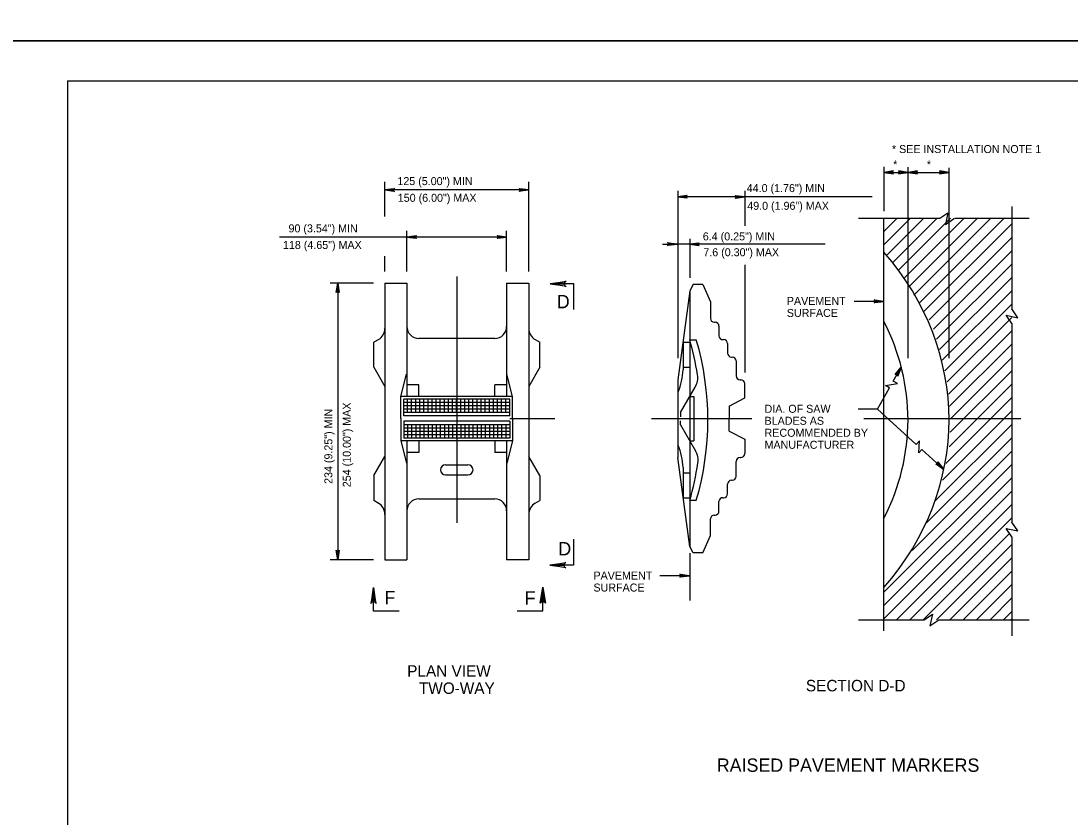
# Model space of a CAD drawing. Extents: x 639362 to 641108, y 298458 to 299646.
# Drawn here: x 640225.9 to 640619.2, y 298760.6 to 299059.1 of the extents above; entities that cross this region are included whole.
import ezdxf

# ---------------------------------------------------------------- set-up
doc = ezdxf.new("R2010")
doc.units = 0
for name, color, linetype in [('1', 7, 'Continuous'), ('2', 7, 'Continuous'), ('3', 7, 'Continuous'), ('PLT-BNDY', 7, 'Continuous')]:
    doc.layers.add(name, color=color, linetype=linetype)

# ---------------------------------------------------------------- blocks, each defined once
blk = doc.blocks.new('RARROW')
at = {"layer": '3'}
blk.add_lwpolyline([(-2.2695, 0.285), (-2.184875, 0.12075), (0, 0), (-2.2695, 0.285), (-2.38575, 0.384625), (0, 0), (-2.183125, -0.108), (-2.262875, -0.2705), (0, 0), (-2.38575, -0.379125), (-2.262875, -0.2705)], dxfattribs=at)

msp = doc.modelspace()

# ---------------------------------------------------------------- linework, layer by layer
at = {"layer": '1'}
for q in [(641029.31, 299036.63), (640243.31, 298472.63)]:
    msp.add_line((640243.31, 299036.63), q, dxfattribs=at)
at = {"layer": '2'}
for p, q in [((640549.4, 299004.47), (640549.4, 298987.85)), ((640549.4, 299002.33), (640573.84, 299002.33)), ((640558.46, 298932.66), (640558.46, 299004.34)), ((640573.84, 298932.66), (640573.84, 299004.07)), ((640362.29, 298985.8), (640362.29, 298998.87)), ((640416.24, 298965.15), (640416.24, 298998.87)), ((640416.24, 298995.79), (640362.29, 298995.79)), ((640472.13, 298995.38), (640472.13, 298932.71)), ((640497.22, 298995.38), (640497.22, 298982.37)), ((640544.99, 298993.14), (640472.13, 298993.14)), ((640570.36, 298985.17), (640573.44, 298987.22)), ((640573.44, 298987.22), (640572.53, 298982.82)), ((640597.33, 298989.51), (640597.33, 298951.16)), ((640539.93, 298985.17), (640570.36, 298985.17)), ((640549.4, 298985.16), (640549.41, 298985.17)), ((640549.4, 298980.15), (640554.42, 298985.17)), ((640549.4, 298975.14), (640559.43, 298985.17)), ((640549.4, 298830.51), (640549.4, 298985.17)), ((640550.44, 298971.18), (640564.44, 298985.17)), ((640552.68, 298968.41), (640569.44, 298985.17)), ((640554.92, 298965.64), (640574.45, 298985.17)), ((640556.84, 298962.55), (640579.46, 298985.17)), ((640558.75, 298959.45), (640584.47, 298985.17)), ((640560.66, 298956.35), (640589.48, 298985.17)), ((640562.56, 298953.25), (640594.49, 298985.17)), ((640564.45, 298950.13), (640597.33, 298983.01)), ((640572.53, 298982.82), (640575.83, 298985.17)), ((640576.1, 298985.17), (640603.86, 298985.17)), ((640407.94, 298978.12), (640322.8, 298978.12)), ((640370.59, 298965.15), (640370.59, 298980.4)), ((640407.94, 298965.15), (640407.94, 298980.4)), ((640466.45, 298975.45), (640471.88, 298975.45)), ((640527.35, 298975.45), (640472.13, 298975.45)), ((640476.61, 298977.46), (640476.61, 298962.86)), ((640566.35, 298947.02), (640597.33, 298978)), ((640362.29, 298965.15), (640362.29, 298971)), ((640567.97, 298943.62), (640597.33, 298972.99)), ((640497.22, 298967.65), (640497.22, 298927.34)), ((640569.13, 298939.78), (640597.33, 298967.98)), ((640389.27, 298963.3), (640389.27, 298870.92)), ((640570.29, 298935.93), (640597.33, 298962.97)), ((640357.99, 298960.85), (640341.84, 298960.85)), ((640344.63, 298960.85), (640344.63, 298857.09)), ((640362.29, 298960.85), (640362.29, 298857.09)), ((640362.29, 298960.85), (640370.59, 298960.85)), ((640370.59, 298960.85), (640370.59, 298918.31)), ((640407.94, 298960.85), (640416.24, 298960.85)), ((640407.94, 298960.85), (640407.94, 298918.31)), ((640416.24, 298960.85), (640416.24, 298857.09)), ((640433.12, 298960.62), (640424.24, 298960.62)), ((640433.12, 298951), (640433.12, 298960.62)), ((640477.94, 298960.33), (640476.61, 298957.95)), ((640481.5, 298960.33), (640477.94, 298960.33)), ((640481.5, 298960.33), (640484.36, 298953.79)), ((640476.61, 298957.95), (640472.13, 298924.52)), ((640476.61, 298957.95), (640476.61, 298862.07)), ((640571.3, 298931.94), (640597.33, 298957.97)), ((640484.36, 298953.79), (640484.36, 298947.61)), ((640549.4, 298953.95), (640538.26, 298953.95)), ((640572.26, 298927.89), (640597.33, 298952.96)), ((640599.68, 298947.87), (640597.33, 298951.16)), ((640573.15, 298923.77), (640597.33, 298947.95)), ((640597.33, 298945.7), (640595.28, 298948.78)), ((640595.28, 298948.78), (640599.68, 298947.87)), ((640485.82, 298946.15), (640486.12, 298946.15)), ((640487.58, 298944.69), (640487.58, 298941.1)), ((640573.6, 298919.21), (640597.33, 298942.94)), ((640597.33, 298945.7), (640597.33, 298871.2)), ((640359.85, 298939.63), (640358.14, 298938.65)), ((640403.52, 298940.1), (640375.02, 298940.1)), ((640418.68, 298939.64), (640420.4, 298938.65)), ((640474.15, 298939.56), (640474.15, 298928.37)), ((640476.61, 298939.58), (640479.09, 298939.58)), ((640489.04, 298939.64), (640489.33, 298939.64)), ((640358.14, 298929.29), (640358.14, 298938.65)), ((640420.4, 298929.29), (640420.4, 298938.65)), ((640474.15, 298938.65), (640476.61, 298938.65)), ((640490.79, 298938.18), (640490.79, 298934.59)), ((640574.05, 298914.65), (640597.33, 298937.93)), ((640492.25, 298933.12), (640492.54, 298933.12)), ((640494, 298931.66), (640494, 298926.05)), ((640574.48, 298910.07), (640597.33, 298932.92)), ((640358.14, 298929.29), (640362.29, 298922.1)), ((640420.4, 298929.29), (640416.24, 298922.1)), ((640474.15, 298929.29), (640476.61, 298929.29)), ((640552.95, 298924.08), (640555.93, 298929.36)), ((640574.32, 298904.91), (640597.33, 298927.91)), ((640368.34, 298918.31), (640370.46, 298926.65)), ((640410.2, 298918.31), (640408.08, 298926.65)), ((640472.13, 298924.52), (640472.13, 298895.5)), ((640495.47, 298924.59), (640495.76, 298924.59)), ((640497.22, 298917.76), (640497.22, 298923.13)), ((640550.04, 298922.49), (640554.48, 298923.21)), ((640554.48, 298923.21), (640552.95, 298924.08)), ((640375.02, 298922.74), (640370.59, 298922.74)), ((640375.02, 298918.31), (640375.02, 298922.74)), ((640403.52, 298918.31), (640403.52, 298922.74)), ((640407.94, 298922.74), (640403.52, 298922.74)), ((640473.12, 298912.33), (640478.66, 298921.81)), ((640546.99, 298913.52), (640551.57, 298921.63)), ((640551.57, 298921.63), (640550.04, 298922.49)), ((640573.89, 298899.46), (640597.33, 298922.91)), ((640410.2, 298918.31), (640368.34, 298918.31)), ((640368.34, 298910.01), (640368.34, 298918.31)), ((640369.4, 298911.01), (640369.4, 298917.31)), ((640409.14, 298917.31), (640369.4, 298917.31)), ((640409.14, 298916.07), (640369.4, 298916.07)), ((640370.8, 298912.33), (640370.8, 298917.31)), ((640372.34, 298912.33), (640372.34, 298917.31)), ((640373.87, 298912.33), (640373.87, 298917.31)), ((640375.41, 298912.33), (640375.41, 298917.31)), ((640376.94, 298912.33), (640376.94, 298917.31)), ((640378.48, 298912.33), (640378.48, 298917.31)), ((640380.01, 298912.33), (640380.01, 298917.31)), ((640381.54, 298912.33), (640381.54, 298917.31)), ((640383.07, 298912.33), (640383.07, 298917.31)), ((640384.61, 298912.33), (640384.61, 298917.31)), ((640386.14, 298912.33), (640386.14, 298917.31)), ((640387.67, 298912.33), (640387.67, 298917.31)), ((640389.21, 298912.33), (640389.21, 298917.31)), ((640390.74, 298912.33), (640390.74, 298917.31)), ((640392.27, 298912.33), (640392.27, 298917.31)), ((640393.81, 298912.33), (640393.81, 298917.31)), ((640395.34, 298912.33), (640395.34, 298917.31)), ((640396.88, 298912.33), (640396.88, 298917.31)), ((640398.41, 298912.33), (640398.41, 298917.31)), ((640399.94, 298912.33), (640399.94, 298917.31)), ((640401.48, 298912.33), (640401.48, 298917.31)), ((640403.01, 298912.33), (640403.01, 298917.31)), ((640404.54, 298912.33), (640404.54, 298917.31)), ((640406.08, 298912.33), (640406.08, 298917.31)), ((640407.61, 298912.33), (640407.61, 298917.31)), ((640409.14, 298911.01), (640409.14, 298917.31)), ((640410.2, 298910.01), (640410.2, 298918.31)), ((640476.61, 298918.31), (640478.16, 298918.31)), ((640478.16, 298918.31), (640478.16, 298901.71)), ((640491.46, 298914.75), (640497.22, 298917.76)), ((640572.62, 298893.19), (640597.33, 298917.9)), ((640409.14, 298914.82), (640369.4, 298914.82)), ((640409.14, 298913.58), (640369.4, 298913.58)), ((640409.14, 298912.33), (640369.4, 298912.33)), ((640473.12, 298912.33), (640473.12, 298910.75)), ((640491.46, 298914.75), (640491.46, 298910.01)), ((640546.99, 298913.52), (640539.77, 298913.52)), ((640546.99, 298913.52), (640561.54, 298900.35)), ((640571.36, 298886.91), (640597.33, 298912.89)), ((640368.34, 298910.01), (640368.34, 298901.71)), ((640409.14, 298911.01), (640369.4, 298911.01)), ((640409.14, 298909.01), (640369.4, 298909.01)), ((640369.4, 298909.01), (640369.4, 298902.7)), ((640409.14, 298907.68), (640369.4, 298907.68)), ((640370.8, 298907.68), (640370.8, 298902.7)), ((640372.34, 298907.68), (640372.34, 298902.7)), ((640373.87, 298907.68), (640373.87, 298902.7)), ((640375.41, 298907.68), (640375.41, 298902.7)), ((640376.94, 298907.68), (640376.94, 298902.7)), ((640378.48, 298907.68), (640378.48, 298902.7)), ((640380.01, 298907.68), (640380.01, 298902.7)), ((640381.54, 298907.68), (640381.54, 298902.7)), ((640383.07, 298907.68), (640383.07, 298902.7)), ((640384.61, 298907.68), (640384.61, 298902.7)), ((640386.14, 298907.68), (640386.14, 298902.7)), ((640387.67, 298907.68), (640387.67, 298902.7)), ((640389.21, 298907.68), (640389.21, 298902.7)), ((640390.74, 298907.68), (640390.74, 298902.7)), ((640392.27, 298907.68), (640392.27, 298902.7)), ((640393.81, 298907.68), (640393.81, 298902.7)), ((640395.34, 298907.68), (640395.34, 298902.7)), ((640396.88, 298907.68), (640396.88, 298902.7)), ((640398.41, 298907.68), (640398.41, 298902.7)), ((640399.94, 298907.68), (640399.94, 298902.7)), ((640401.48, 298907.68), (640401.48, 298902.7)), ((640403.01, 298907.68), (640403.01, 298902.7)), ((640404.54, 298907.68), (640404.54, 298902.7)), ((640406.08, 298907.68), (640406.08, 298902.7)), ((640407.61, 298907.68), (640407.61, 298902.7)), ((640409.14, 298910.01), (640425.99, 298910.01)), ((640409.14, 298909.01), (640409.14, 298902.7)), ((640410.2, 298910.01), (640410.2, 298901.71)), ((640462.34, 298910.01), (640499.92, 298910.01)), ((640473.12, 298907.68), (640473.12, 298909.18)), ((640473.12, 298907.68), (640478.79, 298897.99)), ((640491.46, 298905.27), (640491.46, 298910.01)), ((640541.88, 298910.01), (640600.72, 298910.01)), ((640568.78, 298879.32), (640597.33, 298907.88)), ((640409.14, 298906.44), (640369.4, 298906.44)), ((640409.14, 298905.2), (640369.4, 298905.2)), ((640409.14, 298903.95), (640369.4, 298903.95)), ((640491.46, 298905.27), (640497.22, 298902.26)), ((640410.2, 298901.71), (640368.34, 298901.71)), ((640368.34, 298901.71), (640370.46, 298893.37)), ((640409.14, 298902.7), (640369.4, 298902.7)), ((640370.59, 298901.71), (640370.59, 298857.09)), ((640375.02, 298901.71), (640375.02, 298897.28)), ((640403.52, 298901.71), (640403.52, 298897.28)), ((640407.94, 298901.71), (640407.94, 298857.09)), ((640410.2, 298901.71), (640408.08, 298893.37)), ((640476.61, 298901.71), (640478.16, 298901.71)), ((640497.22, 298902.26), (640497.22, 298896.89)), ((640562.72, 298901.66), (640561.54, 298900.35)), ((640562.46, 298897.16), (640562.72, 298901.66)), ((640565.39, 298870.93), (640597.33, 298902.87)), ((640358.14, 298888.65), (640362.29, 298895.84)), ((640375.02, 298897.28), (640370.59, 298897.28)), ((640407.94, 298897.28), (640403.52, 298897.28)), ((640420.4, 298888.65), (640416.24, 298895.84)), ((640560.07, 298860.6), (640597.33, 298897.86)), ((640563.63, 298898.47), (640562.46, 298897.16)), ((640563.63, 298898.47), (640571.91, 298890.98)), ((640385.09, 298892.72), (640393.45, 298892.72)), ((640476.61, 298862.07), (640472.13, 298895.5)), ((640474.15, 298891.65), (640474.15, 298880.47)), ((640494, 298888.36), (640494, 298893.97)), ((640495.47, 298895.43), (640495.76, 298895.43)), ((640549.4, 298844.92), (640597.33, 298892.85)), ((640358.14, 298888.65), (640358.14, 298879.3)), ((640385.09, 298888.9), (640393.45, 298888.9)), ((640420.4, 298888.65), (640420.4, 298879.3)), ((640474.15, 298889.69), (640476.61, 298889.69)), ((640549.4, 298839.91), (640597.33, 298887.85)), ((640490.79, 298881.84), (640490.79, 298885.43)), ((640492.25, 298886.9), (640492.54, 298886.9)), ((640375.02, 298879.92), (640403.52, 298879.92)), ((640474.15, 298880.34), (640476.61, 298880.34)), ((640489.04, 298880.38), (640489.33, 298880.38)), ((640549.4, 298834.9), (640597.33, 298882.84)), ((640359.85, 298878.31), (640358.14, 298879.3)), ((640418.68, 298878.31), (640420.4, 298879.3)), ((640476.61, 298879.4), (640479.09, 298879.4)), ((640487.58, 298875.33), (640487.58, 298878.92)), ((640554.15, 298834.64), (640597.33, 298877.83)), ((640484.36, 298866.23), (640484.36, 298872.41)), ((640485.82, 298873.87), (640486.12, 298873.87)), ((640559.16, 298834.64), (640597.33, 298872.82)), ((640597.33, 298865.73), (640595.28, 298868.81)), ((640595.28, 298868.81), (640599.68, 298867.91)), ((640599.68, 298867.91), (640597.33, 298871.2)), ((640433, 298864.87), (640433, 298855.12)), ((640481.5, 298859.69), (640484.36, 298866.23)), ((640564.17, 298834.64), (640596.5, 298866.98)), ((640597.33, 298865.73), (640597.33, 298828.63)), ((640477.94, 298859.69), (640476.61, 298862.07)), ((640569.17, 298834.64), (640597.33, 298862.8)), ((640357.99, 298857.09), (640341.84, 298857.09)), ((640362.29, 298857.09), (640370.59, 298857.09)), ((640416.24, 298857.09), (640407.94, 298857.09)), ((640476.61, 298859.59), (640476.61, 298841.86)), ((640481.5, 298859.69), (640477.94, 298859.69)), ((640574.18, 298834.64), (640597.33, 298857.79)), ((640433, 298855.12), (640424.12, 298855.12)), ((640579.19, 298834.64), (640597.33, 298852.78)), ((640476.51, 298851.1), (640465.37, 298851.1)), ((640358.03, 298837.85), (640358.03, 298846.73)), ((640421.48, 298838.01), (640421.48, 298846.88)), ((640584.2, 298834.64), (640597.33, 298847.78)), ((640589.21, 298834.64), (640597.33, 298842.77)), ((640367.65, 298837.85), (640358.03, 298837.85)), ((640411.85, 298838.01), (640421.48, 298838.01)), ((640564.51, 298834.64), (640567.59, 298836.69)), ((640567.59, 298836.69), (640566.69, 298832.3)), ((640594.22, 298834.64), (640597.33, 298837.76)), ((640539.93, 298834.64), (640564.51, 298834.64)), ((640566.69, 298832.3), (640569.98, 298834.64)), ((640569.98, 298834.64), (640603.86, 298834.64)), ((640596.97, 298834.64), (640597.33, 298834.96))]:
    msp.add_line(p, q, dxfattribs=at)
for points in [[(640552.8, 299002.76), (640552.67, 299002.52), (640549.4, 299002.33), (640552.8, 299002.76), (640552.97, 299002.91), (640549.4, 299002.33), (640552.67, 299002.17), (640552.79, 299001.93), (640549.4, 299002.33), (640552.97, 299001.77), (640552.79, 299001.93)], [(640555.06, 299001.91), (640555.18, 299002.15), (640558.46, 299002.33), (640555.06, 299001.91), (640554.88, 299001.76), (640558.46, 299002.33), (640555.18, 299002.5), (640555.07, 299002.74), (640558.46, 299002.33), (640554.88, 299002.9), (640555.07, 299002.74)], [(640561.87, 299002.76), (640561.74, 299002.52), (640558.46, 299002.33), (640561.87, 299002.76), (640562.04, 299002.91), (640558.46, 299002.33), (640561.73, 299002.17), (640561.85, 299001.93), (640558.46, 299002.33), (640562.04, 299001.77), (640561.85, 299001.93)], [(640570.44, 299001.91), (640570.56, 299002.15), (640573.84, 299002.33), (640570.44, 299001.91), (640570.26, 299001.76), (640573.84, 299002.33), (640570.57, 299002.5), (640570.45, 299002.74), (640573.84, 299002.33), (640570.26, 299002.9), (640570.45, 299002.74)], [(640365.7, 298995.37), (640365.57, 298995.61), (640362.29, 298995.79), (640365.7, 298995.37), (640365.87, 298995.22), (640362.29, 298995.79), (640365.56, 298995.96), (640365.68, 298996.2), (640362.29, 298995.79), (640365.87, 298996.36), (640365.68, 298996.2)], [(640412.84, 298996.22), (640412.97, 298995.97), (640416.24, 298995.79), (640412.84, 298996.22), (640412.66, 298996.37), (640416.24, 298995.79), (640412.97, 298995.63), (640412.85, 298995.39), (640416.24, 298995.79), (640412.66, 298995.22), (640412.85, 298995.39)], [(640475.5, 298992.8), (640475.37, 298993.04), (640472.1, 298993.23), (640475.5, 298992.8), (640475.67, 298992.65), (640472.1, 298993.23), (640475.37, 298993.39), (640475.49, 298993.63), (640472.1, 298993.23), (640475.67, 298993.79), (640475.49, 298993.63)], [(640493.81, 298993.57), (640493.94, 298993.32), (640497.22, 298993.14), (640493.81, 298993.57), (640493.64, 298993.72), (640497.22, 298993.14), (640493.94, 298992.98), (640493.82, 298992.73), (640497.22, 298993.14), (640493.64, 298992.57), (640493.82, 298992.73)], [(640374, 298977.7), (640373.87, 298977.94), (640370.59, 298978.12), (640374, 298977.7), (640374.17, 298977.55), (640370.59, 298978.12), (640373.87, 298978.29), (640373.98, 298978.53), (640370.59, 298978.12), (640374.17, 298978.69), (640373.98, 298978.53)], [(640404.54, 298978.55), (640404.67, 298978.31), (640407.94, 298978.12), (640404.54, 298978.55), (640404.36, 298978.7), (640407.94, 298978.12), (640404.67, 298977.96), (640404.55, 298977.72), (640407.94, 298978.12), (640404.36, 298977.56), (640404.55, 298977.72)], [(640468.48, 298975.87), (640468.6, 298975.63), (640471.88, 298975.45), (640468.48, 298975.87), (640468.3, 298976.02), (640471.88, 298975.45), (640468.61, 298975.28), (640468.49, 298975.04), (640471.88, 298975.45), (640468.3, 298974.88), (640468.49, 298975.04)], [(640480.04, 298975), (640479.91, 298975.25), (640476.63, 298975.43), (640480.04, 298975), (640480.21, 298974.85), (640476.63, 298975.43), (640479.91, 298975.59), (640480.03, 298975.83), (640476.63, 298975.43), (640480.21, 298976), (640480.03, 298975.83)], [(640344.21, 298957.45), (640344.45, 298957.57), (640344.63, 298960.85), (640344.21, 298957.45), (640344.06, 298957.27), (640344.63, 298960.85), (640344.8, 298957.58), (640345.04, 298957.46), (640344.63, 298960.85), (640345.2, 298957.27), (640345.04, 298957.46)], [(640545.99, 298954.38), (640546.12, 298954.13), (640549.4, 298953.95), (640545.99, 298954.38), (640545.82, 298954.53), (640549.4, 298953.95), (640546.12, 298953.78), (640546, 298953.54), (640549.4, 298953.95), (640545.82, 298953.38), (640546, 298953.54)], [(640553.9, 298926.6), (640554.18, 298926.59), (640555.93, 298929.36), (640553.9, 298926.6), (640553.68, 298926.52), (640555.93, 298929.36), (640554.48, 298926.43), (640554.63, 298926.2), (640555.93, 298929.36), (640554.68, 298925.96), (640554.63, 298926.2)], [(640569.66, 298893.57), (640569.58, 298893.3), (640571.91, 298890.98), (640569.66, 298893.57), (640569.62, 298893.79), (640571.91, 298890.98), (640569.36, 298893.04), (640569.11, 298892.94), (640571.91, 298890.98), (640568.86, 298892.94), (640569.11, 298892.94)], [(640345.06, 298860.5), (640344.81, 298860.37), (640344.63, 298857.09), (640345.06, 298860.5), (640345.21, 298860.67), (640344.63, 298857.09), (640344.47, 298860.37), (640344.23, 298860.49), (640344.63, 298857.09), (640344.06, 298860.67), (640344.23, 298860.49)], [(640473.1, 298851.53), (640473.23, 298851.28), (640476.51, 298851.1), (640473.1, 298851.53), (640472.93, 298851.68), (640476.51, 298851.1), (640473.23, 298850.94), (640473.11, 298850.7), (640476.51, 298851.1), (640472.93, 298850.53), (640473.11, 298850.7)]]:
    msp.add_lwpolyline(points, dxfattribs=at)
for centre, radius, start, end in [((640485.82, 298947.61), 1.46, 180, 270), ((640357.42, 298943.85), 4.87, 300.0116, 0), ((640375.02, 298944.53), 4.43, 180, 270), ((640403.52, 298944.53), 4.43, 270, 0), ((640421.11, 298943.85), 4.87, 180, 239.9911), ((640486.12, 298944.69), 1.46, 0, 90), ((640372.89, 298909.49), 108, 9.0629, 16.1776), ((640376.74, 298909.49), 106.68, 343.617, 16.384), ((640489.04, 298941.1), 1.46, 180, 270), ((640489.33, 298938.18), 1.46, 0, 90), ((640492.25, 298934.59), 1.46, 180, 270), ((640492.54, 298931.66), 1.46, 0, 90), ((640445.66, 298930.27), 28.55, 338.7062, 356.1981), ((640472.55, 298925.39), 7.08, 329.6797, 9.0629), ((640495.47, 298926.05), 1.46, 180, 270), ((640495.76, 298923.13), 1.46, 0, 90), ((640445.66, 298889.75), 28.55, 3.8019, 21.2938), ((640472.68, 298894.41), 7.08, 351.4083, 30.3164), ((640495.76, 298896.89), 1.46, 270, 0), ((640385.09, 298890.81), 1.91, 90, 270), ((640393.45, 298890.81), 1.91, 270, 90), ((640372.89, 298909.49), 108, 343.8224, 351.4083), ((640495.47, 298893.97), 1.46, 90, 180), ((640492.54, 298888.36), 1.46, 270, 0), ((640492.25, 298885.43), 1.46, 90, 180), ((640375.02, 298875.49), 4.43, 90, 180), ((640403.52, 298875.49), 4.43, 0, 90), ((640489.04, 298878.92), 1.46, 90, 180), ((640489.33, 298881.84), 1.46, 270, 0), ((640357.42, 298874.09), 4.87, 0, 59.9884), ((640421.11, 298874.09), 4.87, 120.0089, 180), ((640485.82, 298872.41), 1.46, 90, 180), ((640486.12, 298875.33), 1.46, 270, 0)]:
    msp.add_arc(centre, radius, start, end, dxfattribs=at)
for major_axis, start_param, end_param in [((120.54, 0), 5.635049, 6.931321), ((105.16, 0), 5.864949, 6.701422)]:
    msp.add_ellipse((640453.3, 298909.56), major_axis=major_axis, ratio=0.86436, start_param=start_param, end_param=end_param, dxfattribs=at)
at = {"layer": 'PLT-BNDY'}
for points in [[(640203.31, 299645.63), (641044.31, 299645.63), (641044.31, 299051.63), (640203.31, 299051.63)], [(640203.31, 299051.63), (641044.31, 299051.63), (641044.31, 298457.63), (640203.31, 298457.63)]]:
    msp.add_lwpolyline(points, close=True, dxfattribs=at)

# ---------------------------------------------------------------- block references
at = {"layer": '2', "xscale": 2.5148695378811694}
for p, yscale, rotation in [((640424.24, 298960.62), 2.618592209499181, 180), ((640424.12, 298855.12), 2.618592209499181, 180), ((640358.03, 298846.73), -2.618592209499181, 90.00000000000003), ((640421.48, 298846.88), 2.618592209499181, 89.99999999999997)]:
    msp.add_blockref('RARROW', p, dxfattribs=dict(at, yscale=yscale, rotation=rotation))

# ---------------------------------------------------------------- texts
at = {"layer": '2'}
for s, height, p in [('* SEE INSTALLATION NOTE 1', 3, (640552.45, 299009.6)), ('*', 3, (640552.91, 299003.83)), ('*', 3, (640565.53, 299003.83)), ('125 (5.00") MIN', 3, (640367, 298997.59)), ('44.0 (1.76") MIN', 3, (640498, 298994.97)), ('150 (6.00") MAX', 3, (640367.14, 298991.33)), ('49.0 (1.96") MAX', 3, (640498.18, 298988.33)), ('90 (3.54") MIN', 3, (640326.18, 298979.86)), ('6.4 (0.25") MIN', 3, (640481.52, 298976.85)), ('118 (4.65") MAX', 3, (640324.1, 298973.64)), ('7.6 (0.30") MAX', 3, (640481.71, 298970.91)), ('D', 5, (640426.77, 298951.4)), ('PAVEMENT', 3, (640513.02, 298952.65)), ('SURFACE', 3, (640513.02, 298948.15)), ('DIA. OF SAW', 3, (640504.67, 298912.22)), ('BLADES AS', 3, (640504.67, 298907.72)), ('RECOMMENDED BY', 3, (640504.67, 298903.22)), ('MANUFACTURER', 3, (640504.67, 298898.72)), ('D', 5, (640427.35, 298858.75)), ('PAVEMENT', 3, (640440.51, 298849.68)), ('F', 5, (640362.17, 298840.43)), ('F', 5, (640414.72, 298840.27)), ('SURFACE', 3, (640440.51, 298845.18)), ('PLAN VIEW', 4.3, (640370.68, 298813.25)), ('TWO-WAY', 4.3, (640375.07, 298806.8)), ('SECTION D-D', 4.3, (640520.17, 298807.76)), ('RAISED PAVEMENT MARKERS', 5, (640486.76, 298777.59))]:
    msp.add_text(s, height=height, dxfattribs=at).set_placement(p)
for s, p in [('254 (10.00") MAX', (640349.52, 298884.31)), ('234 (9.25") MIN', (640342.62, 298885.54))]:
    msp.add_text(s, height=3, rotation=90, dxfattribs=at).set_placement(p)

doc.saveas('drawing.dxf')
